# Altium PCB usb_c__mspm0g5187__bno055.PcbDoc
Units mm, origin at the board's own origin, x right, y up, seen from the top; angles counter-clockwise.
Board outline 92 x 60 mm, 2 copper layers (Top, Bottom), stack 0 mm thick; 42 components, 34 nets, 214 pads, 75 vias.
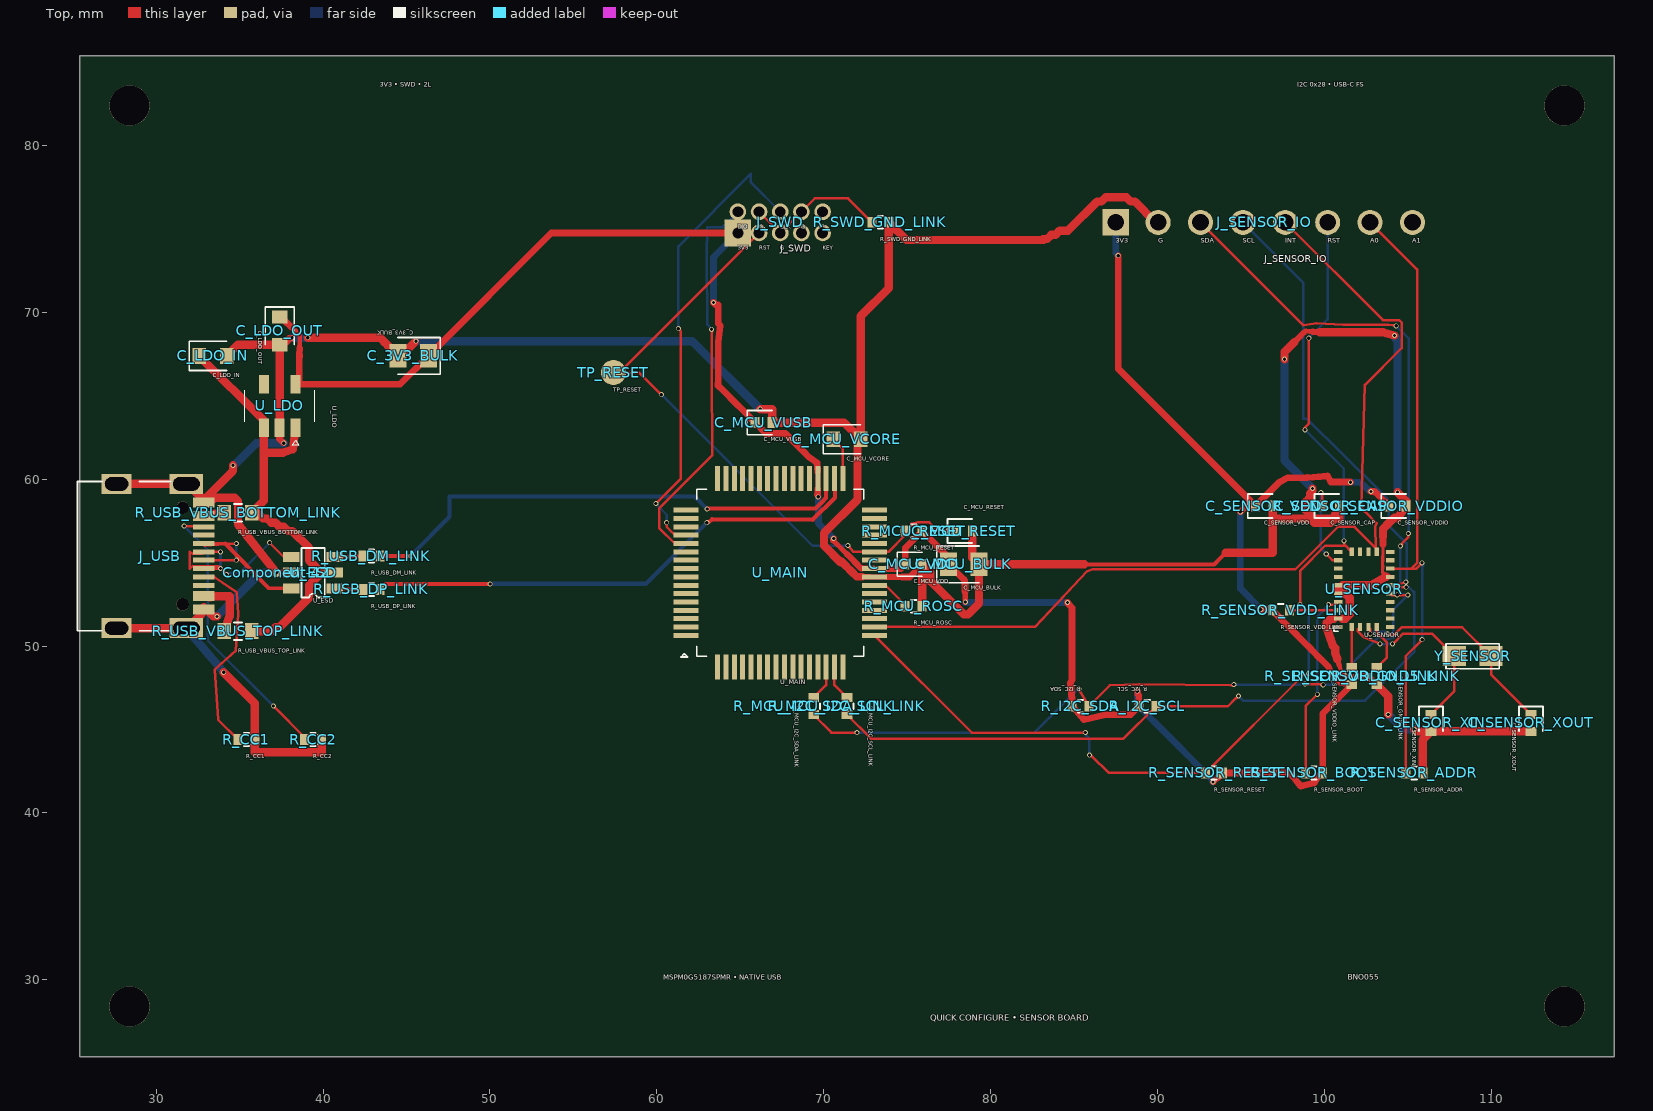
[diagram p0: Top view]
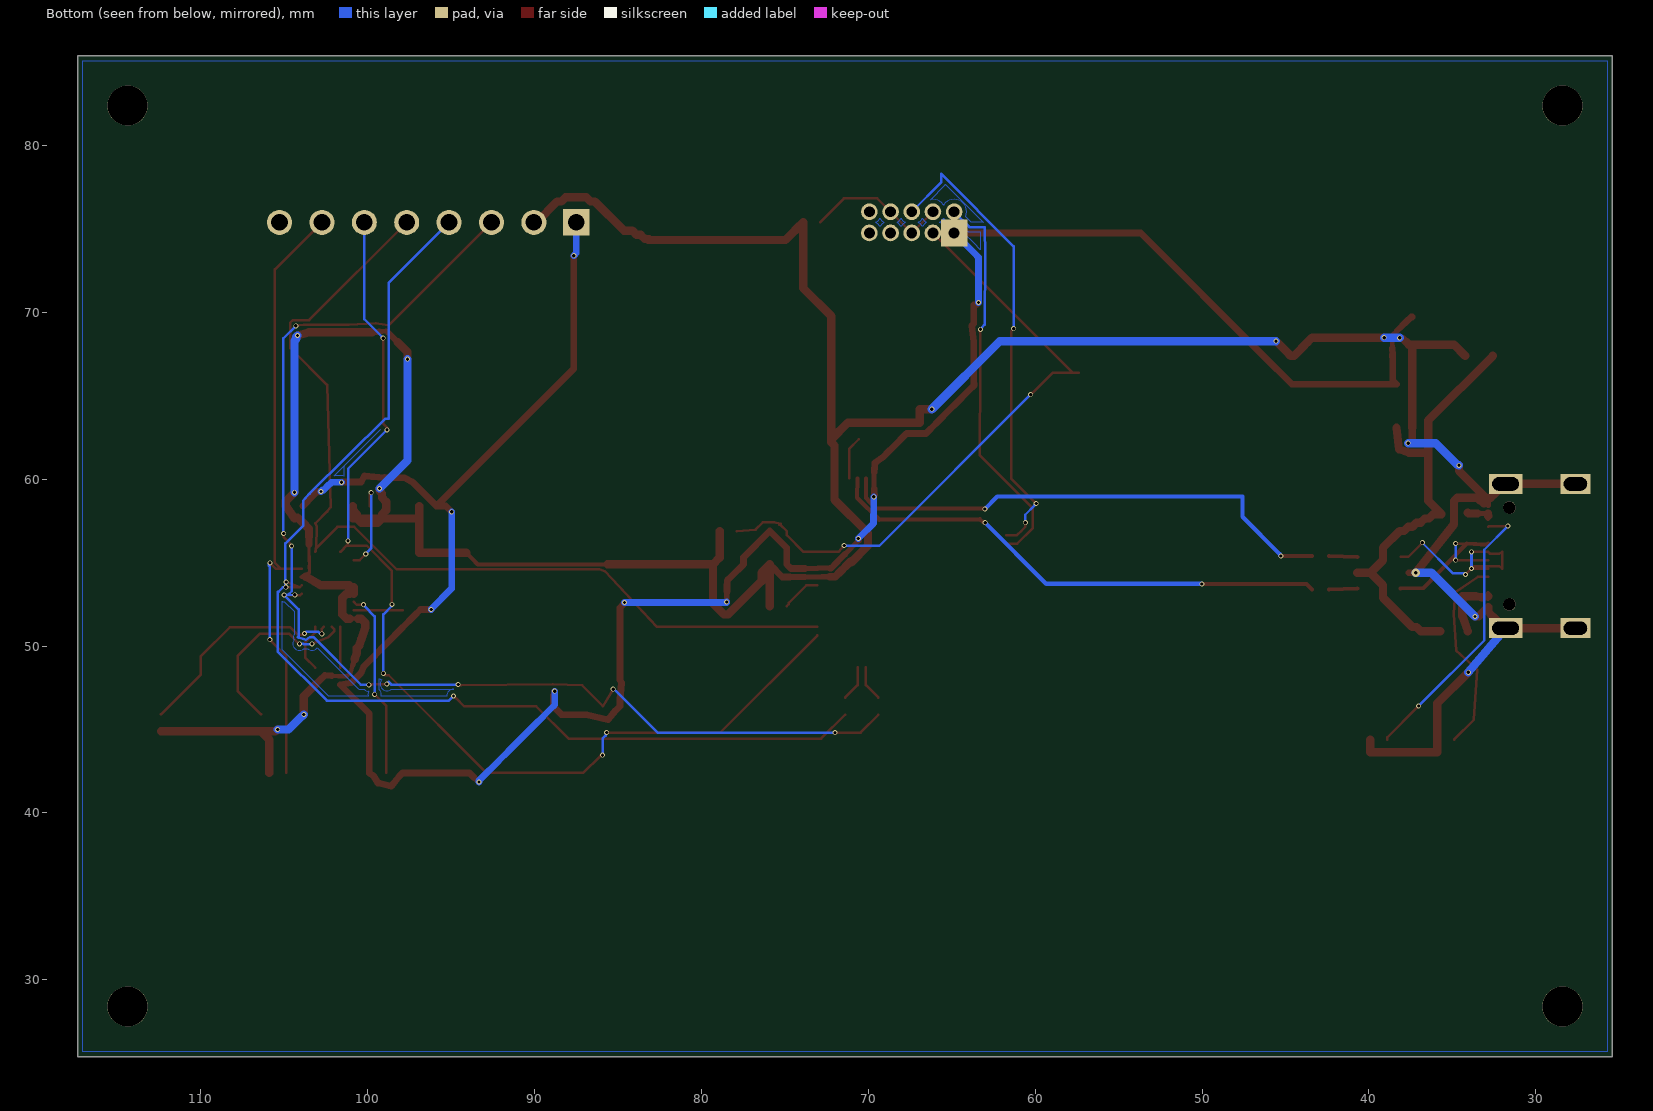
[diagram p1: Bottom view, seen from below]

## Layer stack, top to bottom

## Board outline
25.4,85.4 117.4,85.4 117.4,25.4 25.4,25.4

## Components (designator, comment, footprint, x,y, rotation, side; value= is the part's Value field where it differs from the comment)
C_3V3_BULK "" TSCIRCUIT-2.8500x1.4000mm 45.4,67.4 r180 top
C_LDO_IN "" TSCIRCUIT-2.4500x0.9500mm 33.4,67.4 r0 top
C_LDO_OUT "" TSCIRCUIT-0.9500x2.4500mm 37.4,68.9 r270 top
C_MCU_BULK "" TSCIRCUIT-2.8500x1.4000mm 78.4,54.9 r0 top
C_MCU_RESET "" TSCIRCUIT-1.5600x0.6400mm 78.4,56.9 r0 top
C_MCU_VCORE "" TSCIRCUIT-2.4500x0.9500mm 71.4,62.4 r0 top
C_MCU_VDD "" TSCIRCUIT-1.5600x0.6400mm 75.4,54.9 r0 top
C_MCU_VUSB "" TSCIRCUIT-1.5600x0.6400mm 66.4,63.4 r0 top
C_SENSOR_CAP "" TSCIRCUIT-1.5600x0.6400mm 100.4,58.4 r0 top
C_SENSOR_VDD "" TSCIRCUIT-1.5600x0.6400mm 96.4,58.4 r0 top
C_SENSOR_VDDIO "" TSCIRCUIT-1.5600x0.6400mm 104.4,58.4 r0 top
C_SENSOR_XIN "" TSCIRCUIT-0.6400x1.5600mm 106.4,45.4 r270 top
C_SENSOR_XOUT "" TSCIRCUIT-0.6400x1.5600mm 112.4,45.4 r270 top
Component-42 "" TSCIRCUIT-0.5000x0.5000mm 37.2,54.4 r0 top
J_SENSOR_IO "" TSCIRCUIT-19.2800x1.5000mm 96.4,75.4 r0 top
J_SWD "" TSCIRCUIT-6.0800x2.2700mm 67.4,75.4 r0 top
J_USB "" TSCIRCUIT-6.7732x9.8502mm 30.113,55.4 r90 top
R_CC1 "" TSCIRCUIT-1.5600x0.6400mm 35.4,44.4 r0 top
R_CC2 "" TSCIRCUIT-1.5600x0.6400mm 39.4,44.4 r0 top
R_I2C_SCL "" TSCIRCUIT-1.5600x0.6400mm 89.4,46.4 r180 top
R_I2C_SDA "" TSCIRCUIT-1.5600x0.6400mm 85.4,46.4 r180 top
R_MCU_I2C_SCL_LINK "" TSCIRCUIT-0.6400x1.5600mm 71.4,46.4 r270 top
R_MCU_I2C_SDA_LINK "" TSCIRCUIT-0.6400x1.5600mm 69.4,46.4 r270 top
R_MCU_RESET "" TSCIRCUIT-1.5600x0.6400mm 75.4,56.9 r0 top
R_MCU_ROSC "" TSCIRCUIT-1.5600x0.6400mm 75.4,52.4 r0 top
R_SENSOR_ADDR "" TSCIRCUIT-1.5600x0.6400mm 105.4,42.4 r0 top
R_SENSOR_BOOT "" TSCIRCUIT-1.5600x0.6400mm 99.4,42.4 r0 top
R_SENSOR_GND5_LINK "" TSCIRCUIT-0.6400x1.5600mm 103.15,48.2 r270 top
R_SENSOR_RESET "" TSCIRCUIT-1.5600x0.6400mm 93.4,42.4 r0 top
R_SENSOR_VDD_LINK "" TSCIRCUIT-1.5600x0.6400mm 97.4,52.15 r0 top
R_SENSOR_VDDIO_LINK "" TSCIRCUIT-0.6400x1.5600mm 101.65,48.2 r270 top
R_SWD_GND_LINK "" TSCIRCUIT-1.5600x0.6400mm 73.4,75.4 r0 top
R_USB_DM_LINK "" TSCIRCUIT-1.5600x0.6400mm 42.9,55.4 r0 top
R_USB_DP_LINK "" TSCIRCUIT-1.5600x0.6400mm 42.9,53.4 r0 top
R_USB_VBUS_BOTTOM_LINK "" TSCIRCUIT-2.4500x0.9500mm 34.9,58 r0 top
R_USB_VBUS_TOP_LINK "" TSCIRCUIT-2.4500x0.9500mm 34.9,50.9 r0 top
TP_RESET "" TSCIRCUIT-1.5000x1.5000mm 57.4,66.4 r0 top
U_ESD "" TSCIRCUIT-3.6000x2.5000mm 39.4,54.4 r0 top
U_LDO "" TSCIRCUIT-2.5000x3.7000mm 37.4,64.4 r270 top
U_MAIN "" TSCIRCUIT-12.8000x12.8000mm 67.4,54.4 r0 top
U_SENSOR "" TSCIRCUIT-3.6260x4.9999mm 102.4,53.4 r0 top
Y_SENSOR "" TSCIRCUIT-3.6000x1.2000mm 108.9,49.4 r0 top

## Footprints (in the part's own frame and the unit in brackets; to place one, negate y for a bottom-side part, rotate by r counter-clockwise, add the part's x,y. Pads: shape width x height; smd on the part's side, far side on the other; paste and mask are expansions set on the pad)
TSCIRCUIT-0.5000x0.5000mm [mm]
TSCIRCUIT-0.6400x1.5600mm [mm]
  rect 0.54x0.64 smd: 1(-0.51,0) 2(0.51,0)
  silkscreen extent -0.98,-0.72 0.51,0.72
TSCIRCUIT-0.9500x2.4500mm [mm]
  rect 0.8x0.95 smd: 1(-0.825,0) 2(0.825,0)
  silkscreen extent -1.43,-0.87 0.82,0.88
TSCIRCUIT-1.5000x1.5000mm [mm]
  round 1.5 smd: 1(0,0)
TSCIRCUIT-1.5600x0.6400mm [mm]
  rect 0.54x0.64 smd: 1(-0.51,0) 2(0.51,0)
  silkscreen extent -0.98,-0.72 0.51,0.72
TSCIRCUIT-2.4500x0.9500mm [mm]
  rect 0.8x0.95 smd: 1(-0.825,0) 2(0.825,0)
  silkscreen extent -1.42,-0.87 0.82,0.87
TSCIRCUIT-2.5000x3.7000mm [mm]
  rect 1.1x0.6 smd: 1(1.3,0.95) 2(1.3,0) 3(1.3,-0.95) 4(-1.3,-0.95) 5(-1.3,0.95)
  silkscreen extent -0.95,-2.1 2.35,2.1
TSCIRCUIT-2.8500x1.4000mm [mm]
  rect 1.025x1.4 smd: 1(-0.913,0) 2(0.913,0)
  silkscreen extent -1.63,-1.1 0.91,1.1
TSCIRCUIT-3.6000x1.2000mm [mm]
  rect 1.4x1.2 smd: 1(-1.1,0) 2(1.1,0)
  silkscreen extent -1.6,-0.75 1.6,0.75
TSCIRCUIT-3.6000x2.5000mm [mm]
  rect 1x0.6 smd: 1(-1.3,-0.95) 2(-1.3,0) 3(-1.3,0.95) 4(1.3,0.95) 5(1.3,0) 6(1.3,-0.95)
  silkscreen extent -0.7,-1.49 0.7,1.49
TSCIRCUIT-3.6260x4.9999mm [mm]
  rect 0.5x0.25 smd: 1(-1.563,-2.25) 2(-1.563,-1.75) 3(-1.563,-1.25) 4(-1.563,-0.75) 5(-1.563,-0.25) 6(-1.563,0.25) 7(-1.563,0.75) 8(-1.563,1.25) 9(-1.563,1.75) 10(-1.563,2.25) 15(1.563,2.25) 16(1.563,1.75) 17(1.563,1.25) 18(1.563,0.75) 19(1.563,0.25) 20(1.563,-0.25) 21(1.563,-0.75) 22(1.563,-1.25) 23(1.563,-1.75) 24(1.563,-2.25)
  rect 0.25x0.5 smd: 11(-0.75,2.25) 12(-0.25,2.25) 13(0.25,2.25) 14(0.75,2.25) 25(0.75,-2.25) 26(0.25,-2.25) 27(-0.25,-2.25) 28(-0.75,-2.25)
  silkscreen extent -1.81,-2.5 -1.56,-2.25
TSCIRCUIT-6.0800x2.2700mm [mm]
  rect 1.6x1.6 hole 0.65: 1(-2.54,-0.635)
  round 1 hole 0.65: 2(-2.54,0.635) 3(-1.27,0.635) 4(0,0.635) 5(1.27,0.635) 6(2.54,0.635) 7(2.54,-0.635) 8(1.27,-0.635) 9(0,-0.635) 10(-1.27,-0.635)
TSCIRCUIT-6.7732x9.8502mm [mm]
  rect 0.3x1.3 smd: 1(-3.35,-2.737) 2(-3.05,-2.737) 3(-2.55,-2.737) 4(-2.25,-2.737) 5(-1.75,-2.737) 6(-1.25,-2.737) 7(-0.75,-2.737) 8(-0.25,-2.737) 9(0.25,-2.737) 10(0.75,-2.737) 11(1.25,-2.737) 12(1.75,-2.737) 13(2.55,-2.737) 14(2.25,-2.737) 15(3.35,-2.737) 16(3.05,-2.737)
  rect 1.2x2 hole 0.8 slot 1.6 at 90 deg: 17(-4.325,-1.693) 18(4.325,-1.693)
  rect 1.2x1.8 hole 0.8 slot 1.4 at 90 deg: 19(4.325,2.487) 20(-4.325,2.487)
  round 0.75 hole 0.75 unplated: NPTH-1(-2.9,-1.468) NPTH-2(2.9,-1.468)
  silkscreen extent -4.47,-0.75 4.47,4.83
TSCIRCUIT-12.8000x12.8000mm [mm]
  rect 1.5x0.3 smd: 1(-5.65,-3.75) 2(-5.65,-3.25) 3(-5.65,-2.75) 4(-5.65,-2.25) 5(-5.65,-1.75) 6(-5.65,-1.25) 7(-5.65,-0.75) 8(-5.65,-0.25) 9(-5.65,0.25) 10(-5.65,0.75) 11(-5.65,1.25) 12(-5.65,1.75) 13(-5.65,2.25) 14(-5.65,2.75) 15(-5.65,3.25) 16(-5.65,3.75) 33(5.65,3.75) 34(5.65,3.25) 35(5.65,2.75) 36(5.65,2.25) 37(5.65,1.75) 38(5.65,1.25) 39(5.65,0.75) 40(5.65,0.25) 41(5.65,-0.25) 42(5.65,-0.75) 43(5.65,-1.25) 44(5.65,-1.75) 45(5.65,-2.25) 46(5.65,-2.75) 47(5.65,-3.25) 48(5.65,-3.75)
  rect 0.3x1.5 smd: 17(-3.75,5.65) 18(-3.25,5.65) 19(-2.75,5.65) 20(-2.25,5.65) 21(-1.75,5.65) 22(-1.25,5.65) 23(-0.75,5.65) 24(-0.25,5.65) 25(0.25,5.65) 26(0.75,5.65) 27(1.25,5.65) 28(1.75,5.65) 29(2.25,5.65) 30(2.75,5.65) 31(3.25,5.65) 32(3.75,5.65) 49(3.75,-5.65) 50(3.25,-5.65) 51(2.75,-5.65) 52(2.25,-5.65) 53(1.75,-5.65) 54(1.25,-5.65) 55(0.75,-5.65) 56(0.25,-5.65) 57(-0.25,-5.65) 58(-0.75,-5.65) 59(-1.25,-5.65) 60(-1.75,-5.65) 61(-2.25,-5.65) 62(-2.75,-5.65) 63(-3.25,-5.65) 64(-3.75,-5.65)
  silkscreen extent -5.95,-5.05 5,5
TSCIRCUIT-19.2800x1.5000mm [mm]
  rect 1.6x1.6 hole 1: 1(-8.89,0)
  round 1.5 hole 1: 2(-6.35,0) 3(-3.81,0) 4(-1.27,0) 5(1.27,0) 6(3.81,0) 7(6.35,0) 8(8.89,0)

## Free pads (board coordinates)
  round 2.4 hole 2.4 unplated: NPTH-3(28.4,28.4) NPTH-4(114.4,28.4) NPTH-5(28.4,82.4) NPTH-6(114.4,82.4)

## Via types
v1: diameter 0.3, hole 0.2, Top to Bottom, 74 vias
v2: diameter 0.5, hole 0.2, Top to Bottom, 1 vias

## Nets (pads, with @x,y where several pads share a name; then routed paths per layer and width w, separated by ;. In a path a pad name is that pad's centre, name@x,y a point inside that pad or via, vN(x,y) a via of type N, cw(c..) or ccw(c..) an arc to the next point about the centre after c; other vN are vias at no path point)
".J_SWD > .pin2 to .U_MAIN > .pin12": J_SWD.2 U_MAIN.12 | length 23.7
  Top w0.15: U_MAIN.12 61.077,56.15 60.139,57.089 60.139,58.257 63.316,61.435 63.28,66.534 63.285,68.668 63.316,68.934 63.316,68.986 v1(63.28,68.991)
  Bottom w0.15: v1(63.28,68.991) 63.028,69.274 63.003,73.368 63.028,75.122 63.947,75.122 J_SWD.2
".J_SWD > .pin4 to .U_MAIN > .pin13": J_SWD.4 U_MAIN.13 | length 28.3
  Top w0.15: v1(59.946,58.55) 61.441,60.045 61.441,68.856 61.441,68.875 v1(61.291,69.025) ; v1(60.595,57.398) 60.595,57.154 60.843,56.887 61.098,56.649 U_MAIN.13
  Bottom w0.15: v1(59.946,58.55) 60.051,58.445 60.051,58.421 60.595,57.877 v1(60.595,57.398) ; v1(61.291,69.025) 61.291,73.965 65.628,78.302 65.628,77.807 J_SWD.4
".U_MAIN > .pin42 to .R_MCU_ROSC > .pin1": R_MCU_ROSC.1 U_MAIN.42 | length 2.4
  Top w0.15: U_MAIN.42 73.719,53.65 74.769,52.6 74.769,52.521 R_MCU_ROSC.1
".U_SENSOR > .CAP to .C_SENSOR_CAP > .pin1": C_SENSOR_CAP.1 U_SENSOR.9 | length 5.5
  Top w0.15: v1(99.799,59.199) 99.829,59.171 99.829,59.125 99.89,59.063 C_SENSOR_CAP.1 ; v1(100.125,55.523) 100.498,55.15 U_SENSOR.9
  Bottom w0.15: v1(99.799,59.199) 99.8,55.861 100.089,55.572 100.089,55.559 v1(100.125,55.523)
BNO055_GND5_LOCAL: R_SENSOR_GND5_LINK.1 U_SENSOR.25 | length 2.9
  Top w0.15: R_SENSOR_GND5_LINK.1 103.76,49.32 103.756,50.209 103.151,50.818 U_SENSOR.25
BNO055_VDD_LOCAL: R_SENSOR_VDD_LINK.2 U_SENSOR.3 | length 2.9
  Top w0.15: R_SENSOR_VDD_LINK.2 U_SENSOR.3@100.837,52.15
BNO055_VDDIO_LOCAL: R_SENSOR_VDDIO_LINK.1 U_SENSOR.28 | length 2.4
  Top w0.15: R_SENSOR_VDDIO_LINK.1 U_SENSOR.28
GND: C_3V3_BULK.2 C_LDO_IN.2 C_LDO_OUT.2 C_MCU_BULK.2 C_MCU_RESET.2 C_MCU_VCORE.2 C_MCU_VDD.2 C_MCU_VUSB.2 C_SENSOR_CAP.2 C_SENSOR_VDD.2 C_SENSOR_VDDIO.2 C_SENSOR_XIN.2 C_SENSOR_XOUT.2 J_SENSOR_IO.2 J_USB.1 J_USB.2 J_USB.15 J_USB.16 J_USB.17 J_USB.18 J_USB.19 J_USB.20 R_CC1.2 R_CC2.2 R_MCU_ROSC.2 R_SENSOR_ADDR.2 R_SENSOR_GND5_LINK.2 R_SWD_GND_LINK.2 U_ESD.2 U_LDO.2 U_MAIN.41 U_SENSOR.2 U_SENSOR.5 U_SENSOR.6 U_SENSOR.18 | length 241.4
  Top w0.188: 103.506,54.823 103.512,55.247 103.518,55.67 103.523,56.093
  Top w0.2: 103.506,54.823 103.5,54.4 103.889,54.224 U_SENSOR.18
  Top w0.25: 85.632,54.9 86.118,54.9 86.604,54.9 87.09,54.9 87.577,54.9 88.063,54.9 88.549,54.9 89.035,54.9 89.521,54.9 90.007,54.9 90.493,54.9 90.979,54.9 91.466,54.9 91.952,54.9 92.438,54.9 92.924,54.9 93.41,54.9 93.76,55.25 94.11,55.6 ; U_SENSOR.2@100.587,51.65 U_SENSOR.2 101.087,51.65 ; U_SENSOR.5 101.087,53.15 ; 100.837,53.525 U_SENSOR.6 100.931,53.65 101.024,53.65 101.087,53.65 101.118,53.65 ; 100.918,48.806 101.05,48.4 101.25,48.2 101.75,48.2 102.165,48.225 ; U_SENSOR.18@103.713,54.15 U_SENSOR.18
  Top w0.275: J_USB.16 J_USB.16@33.1,58.5
  Top w0.3: J_USB.1@32.699,51.9 J_USB.1 J_USB.1@32.849,52.2 ; J_USB.15@32.699,58.9 J_USB.15 ; J_USB.2 J_USB.1@32.999,52.2 ; J_USB.16@32.849,58.6 J_USB.15 ; J_USB.15@32.999,58.9 J_USB.15 ; U_MAIN.41@72.769,54.15 72.863,54.15 72.956,54.15 U_MAIN.41 73.144,54.15 73.237,54.15 73.331,54.15 73.425,54.15 73.519,54.15 73.612,54.15 73.706,54.15 U_MAIN.41@73.8,54.15
  Top w0.312: 98.795,68.806 98.9,68.89 99.323,68.848 ; 100.786,49.211 100.918,48.806
  Top w0.32: 72.3,54.156 72.376,54.155 U_MAIN.41@72.769,54.15
  Top w0.325: J_USB.16 J_USB.16@32.849,58.6
  Top w0.35: v1@37.624,62.19 v1(37.643,62.171) ; 37.968,68.441 38.124,68.441 v1(38.153,68.477) ; 98.503,68.514 98.795,68.806
  Top w0.375: 37.4,62.417 37.624,62.193 v1@37.624,62.19 ; 45.429,68.145 45.435,68.145 v1(45.568,68.278) ; U_MAIN.41@73.8,54.15 74.253,54.15 74.707,54.15 ; 98.211,68.222 98.503,68.514 ; 102.165,48.225 102.58,48.25
  Top w0.4: J_USB.16@33.1,58.5 J_USB.15@33.3,58.7 ; 37.2,54.4 U_ESD.2@37.6,54.4 ; 74.707,54.15 75.16,54.15 75.41,54.4 75.66,54.65 C_MCU_VDD.2 ; 99.323,68.848 99.746,68.806 ; 102.58,48.25 102.865,47.97 R_SENSOR_GND5_LINK.2
  Top w0.425: C_LDO_OUT.2@37.785,68.258 37.968,68.441 ; 103.523,56.093 103.524,56.561
  Top w0.45: 37.4,62.417 37.4,62.758 U_LDO.2 ; 71.983,54.16 72.3,54.156
  Top w0.475: 71.351,54.792 71.667,54.476 71.983,54.16
  Top w0.5: J_USB.20 J_USB.17 31.874,51.075 32.474,51.675 32.699,51.9 ; J_USB.19 J_USB.18 31.874,59.725 32.474,59.125 32.699,58.9 ; J_USB.1@32.849,52.2 J_USB.2 ; J_USB.1@32.999,52.2 33.42,51.779 v1(33.639,51.779) ; 32.999,58.9 34.603,60.504 v1(34.603,60.841) ; J_USB.15@33.3,58.7 33.5,58.9 34.7,58.9 34.9,58.7 34.9,57.3 37.2,54.4 ; v1(34.043,48.435) 35.91,46.568 R_CC1.2 35.91,43.65 39.91,43.65 R_CC2.2 ; C_LDO_IN.2 34.9,68.075 C_LDO_OUT.2 ; U_LDO.2 C_LDO_OUT.2 ; C_LDO_OUT.2@37.785,68.258 37.603,68.075 C_LDO_OUT.2 ; v1(39.081,68.491) 39.56,68.491 40.04,68.491 40.519,68.491 40.999,68.491 41.478,68.491 41.958,68.491 42.437,68.491 42.917,68.491 43.396,68.491 43.669,68.218 43.942,67.946 44.215,67.673 C_3V3_BULK.2 44.683,67.4 44.932,67.648 45.18,67.897 45.429,68.145 ; v1(66.2,64.2) 66.91,64.2 C_MCU_VUSB.2 71.225,63.4 C_MCU_VCORE.2 ; 71.351,54.792 71.035,55.108 71.025,55.098 71.025,55.025 70.025,56.025 70.025,56.775 72.025,58.775 72.025,62.025 72.225,62.225 C_MCU_VCORE.2 ; R_MCU_ROSC.2 C_MCU_VDD.2 75.91,54.89 76.4,54.4 76.4,53.9 78.4,51.9 78.65,51.9 79.313,52.563 C_MCU_BULK.2 ; C_MCU_RESET.2 78.91,55.303 C_MCU_BULK.2 ; 85.632,54.9 85.146,54.9 84.66,54.9 84.174,54.9 83.688,54.9 83.201,54.9 82.715,54.9 82.229,54.9 81.743,54.9 81.257,54.9 80.771,54.9 80.285,54.9 79.799,54.9 C_MCU_BULK.2 ; J_SENSOR_IO.2 89.9,75.4 88.65,76.65 88.4,76.65 88.15,76.9 86.9,76.9 86.65,76.65 86.4,76.65 84.65,74.9 84.15,74.9 83.9,74.65 83.65,74.65 83.4,74.4 83.15,74.4 83.15,74.394 83.199,74.345 82.716,74.345 82.233,74.345 81.75,74.345 81.267,74.345 80.784,74.345 80.301,74.345 79.818,74.345 79.335,74.345 78.851,74.345 78.368,74.345 77.885,74.345 77.402,74.345 76.919,74.345 76.436,74.345 75.953,74.345 75.47,74.345 74.987,74.345 74.965,74.345 74.613,74.697 74.262,75.048 R_SWD_GND_LINK.2 73.91,71.464 72.225,69.779 72.225,69.287 72.225,68.795 72.225,68.303 72.225,67.812 72.225,67.32 72.225,66.828 72.225,66.336 72.225,65.844 72.225,65.352 72.225,64.86 72.225,64.368 72.225,63.876 72.225,63.384 72.225,62.892 C_MCU_VCORE.2 ; 94.11,55.6 96.91,55.6 C_SENSOR_VDD.2 96.91,57.65 100.91,57.65 C_SENSOR_CAP.2 100.9,58.4 100.9,58.15 100.65,57.9 100.65,57.65 100.4,57.4 99.4,57.4 99.15,57.65 99.15,57.9 98.9,58.15 98.9,58.65 99.15,58.9 99.15,59.15 99.305,59.305 v1(99.305,59.445) ; v1(97.623,67.197) 97.627,67.201 97.627,67.294 97.627,67.638 97.919,67.93 98.211,68.222 ; 99.746,68.806 100.221,68.806 100.696,68.806 101.172,68.806 101.647,68.806 102.122,68.806 102.598,68.806 103.073,68.806 103.549,68.806 v1(104.214,68.616) ; U_SENSOR.2@100.587,51.65 100.4,51.65 100.15,51.4 100.15,51.15 100.391,50.428 100.523,50.022 100.654,49.89 100.654,49.617 100.786,49.211 ; U_SENSOR.5 100.837,53.275 100.837,53.525 ; 101.087,51.65 101.275,51.65 101.525,51.9 101.525,52.9 101.275,53.15 101.087,53.15 ; 101.118,53.65 101.212,53.65 101.306,53.65 101.4,53.65 101.493,53.65 101.587,53.65 101.994,53.65 102.401,53.65 102.807,53.65 103.65,54.15 103.713,54.15 ; R_SENSOR_GND5_LINK.2 103.837,47.003 v1(103.837,45.907) ; 103.524,56.561 103.525,57.028 103.871,57.371 104.217,57.714 104.4,57.65 C_SENSOR_VDDIO.2 104.91,58.698 v1(104.393,59.215) ; v1(105.4,45) 105.411,44.989 105.441,44.989 105.54,44.89 C_SENSOR_XIN.2 ; R_SENSOR_ADDR.2 105.91,44.4 C_SENSOR_XIN.2 ; C_SENSOR_XOUT.2 C_SENSOR_XIN.2
  Bottom w0.5: J_USB.17 v1(34.043,48.435) ; v1(33.639,51.779) 36.26,54.4 37.2,54.4 ; v1(34.603,60.841) 34.622,60.86 34.687,60.86 35.015,61.188 35.343,61.516 35.67,61.843 35.998,62.171 36.409,62.171 36.82,62.171 37.232,62.171 v1(37.643,62.171) ; v1(38.153,68.477) 39.067,68.477 v1(39.081,68.491) ; v1(45.568,68.278) 46.065,68.278 46.562,68.278 47.059,68.278 47.556,68.278 48.053,68.278 48.55,68.278 49.047,68.278 49.544,68.278 50.041,68.278 50.538,68.278 51.036,68.278 51.533,68.278 52.03,68.278 52.527,68.278 53.024,68.278 53.521,68.278 54.018,68.278 54.515,68.278 55.012,68.278 55.509,68.278 56.006,68.278 56.503,68.278 57,68.278 57.497,68.278 57.994,68.278 58.491,68.278 62.122,68.278 v1(66.2,64.2) ; v1(97.623,67.197) 97.623,66.73 97.623,66.263 97.623,65.796 97.623,65.329 97.623,64.862 97.623,64.395 97.623,63.929 97.623,63.462 97.623,62.995 97.623,62.528 97.623,62.061 97.623,61.594 97.623,61.127 97.934,60.816 98.246,60.504 98.557,60.193 98.868,59.882 99.179,59.571 v1(99.305,59.445) ; v1(103.837,45.907) 103.96,45.784 103.976,45.784 104.759,45 v1(105.4,45) ; v1(104.214,68.616) 104.283,68.547 104.283,68.418 104.393,68.308 104.393,67.83 104.393,67.351 104.393,66.873 104.393,66.394 104.393,65.915 104.393,65.437 104.393,64.958 104.393,64.48 104.393,64.001 104.393,63.522 104.393,63.044 104.393,62.565 104.393,62.087 104.393,61.608 104.393,61.129 104.393,60.651 104.393,60.172 104.393,59.694 v1(104.393,59.215)
MAIN_RESET: C_MCU_RESET.1 J_SWD.10 R_MCU_RESET.1 TP_RESET.1 U_MAIN.38 | length 38.4
  Top w0.15: v1(60.276,65.077) 60.178,65.175 60.157,65.175 58.932,66.4 TP_RESET.1 57.765,66.4 J_SWD.10 ; v1(71.452,56.032) 71.798,55.65 U_MAIN.38 73.889,55.65 74.889,56.651 R_MCU_RESET.1@74.889,56.899 ; R_MCU_RESET.1 75.256,57.266 75.34,57.266 75.256,57.35 75.65,57.423 75.9,57.425 76.15,57.425 76.323,57.425 76.764,56.984 C_MCU_RESET.1
  Bottom w0.15: v1(60.276,65.077) 69.336,56.017 71.271,56.017 71.431,56.017 v1(71.452,56.032)
MCU_I2C_SCL_LOCAL: R_MCU_I2C_SCL_LINK.1 U_MAIN.50 | length 2.2
  Top w0.15: U_MAIN.50 70.65,47.66 R_MCU_I2C_SCL_LINK.1
MCU_I2C_SDA_LOCAL: R_MCU_I2C_SDA_LINK.1 U_MAIN.51 | length 2.2
  Top w0.15: R_MCU_I2C_SDA_LINK.1 70.15,47.66 U_MAIN.51
MSPM0_VCORE: C_MCU_VCORE.1 U_MAIN.32 | length 2.6
  Top w0.15: C_MCU_VCORE.1 71.15,61.825 U_MAIN.32
SENSOR_ADDR0: J_SENSOR_IO.7 R_SENSOR_ADDR.1 U_SENSOR.17 | length 38.4
  Top w0.15: J_SENSOR_IO.7 105.57,72.58 105.57,54.99 105.23,54.65 U_SENSOR.17 105.522,54.65 v1(105.862,54.99) ; R_SENSOR_ADDR.1 104.89,49.403 105.772,50.285 105.772,50.29 v1(105.875,50.393)
  Bottom w0.15: v1(105.862,54.99) 105.94,54.912 105.94,54.819 105.875,54.754 v1(105.875,50.393)
SENSOR_ADDR1: J_SENSOR_IO.8
SENSOR_BOOT: R_SENSOR_BOOT.1 U_SENSOR.4 | length 11.3
  Top w0.15: R_SENSOR_BOOT.1 98.89,46.413 99.588,47.111 v1(99.592,47.115) ; v1(100.262,52.49) 100.67,52.483 U_SENSOR.4
  Bottom w0.15: v1(99.592,47.115) 99.592,51.782 100.212,52.402 100.212,52.433 v1(100.262,52.49)
SENSOR_INT: J_SENSOR_IO.5 U_MAIN.47 U_SENSOR.14 | length 57.9
  Top w0.15: U_MAIN.47 82.673,51.151 85.8,54.5 86.121,54.599 98.266,54.6 100.815,57.147 101.829,57.146 103.114,55.861 103.114,55.686 U_SENSOR.14 103.081,55.936 103.047,57.154 103.15,57.36 102.447,58.063 102.225,58.325 102.447,65.657 104.651,67.861 104.652,69.39 104.495,69.546 103.524,69.546 J_SENSOR_IO.5
SENSOR_RESET: J_SENSOR_IO.6 R_SENSOR_RESET.1 U_MAIN.48 U_SENSOR.11 | length 64.3
  Top w0.15: U_MAIN.48 78.88,44.82 v1(85.69,44.82) ; v1(85.934,43.471) 85.976,43.429 86.066,43.429 87.095,42.4 R_SENSOR_RESET.1 98.749,48.259 98.963,48.259 v1(99.07,48.366) ; v1(98.554,52.509) 98.555,54.513 100.067,56.025 101.273,56.027 U_SENSOR.11 101.19,56.11 v1(101.19,56.311) ; v1(98.847,62.969) 98.818,62.998 98.818,63.073 99.081,63.336 v1(99.081,68.463)
  Bottom w0.15: v1(85.69,44.82) 85.748,44.762 85.748,44.643 85.934,44.456 v1(85.934,43.471) ; v1(98.554,52.509) 98.568,52.495 98.568,52.407 99.07,51.904 v1(99.07,48.366) ; v1(98.847,62.969) 101.182,60.634 101.182,56.438 101.182,56.319 v1(101.19,56.311) ; v1(99.081,68.463) 99.191,68.573 100.21,69.592 J_SENSOR_IO.6
SENSOR_SCL: J_SENSOR_IO.4 R_I2C_SCL.1 R_MCU_I2C_SCL_LINK.2 U_SENSOR.19 | length 69.6
  Top w0.15: R_MCU_I2C_SCL_LINK.2 72.837,44.458 87.966,44.456 R_I2C_SCL.1 94.228,46.4 94.71,46.882 94.737,46.882 v1(94.865,47.01) ; v1(104.9,53.85) U_SENSOR.19@104.073,53.54 ; v1(104.911,53.54) U_SENSOR.19@104.073,53.54 ; U_SENSOR.19@104.073,53.54 U_SENSOR.19 U_SENSOR.19@104.073,53.54
  Bottom w0.15: v1(94.865,47.01) 95.141,46.734 102.458,46.734 105.408,49.684 105.408,53.26 105.354,53.26 105.085,53.53 104.921,53.53 v1(104.9,53.85) ; J_SENSOR_IO.4 98.736,71.794 98.736,63.644 98.947,63.644 103.49,59.149 103.877,58.713 103.877,57.212 104.935,56.153 104.935,53.654 104.935,53.564 v1(104.911,53.54)
SENSOR_SDA: J_SENSOR_IO.3 R_I2C_SDA.1 R_MCU_I2C_SDA_LINK.2 U_SENSOR.20 | length 75.2
  Top w0.15: R_MCU_I2C_SDA_LINK.2 70.47,44.82 71.957,44.82 v1(71.996,44.816) ; v1(85.291,47.423) R_I2C_SDA.1 87.151,47.647 88.93,47.702 94.396,47.643 94.525,47.641 v1(94.583,47.699) ; J_SENSOR_IO.3 98.765,69.225 99.525,69.35 101.158,69.256 103.849,69.253 104.148,69.225 104.287,69.225 v1(104.312,69.198) ; v1(98.861,47.73) 99.75,47.73 99.827,47.653 99.909,47.653 v1(99.941,47.685) ; v1(104.375,53.075) U_SENSOR.20@104.049,53.064 ; v1(104.562,56.004) 104.667,56.109 104.667,56.167 105.047,56.547 v1(105.047,56.756) ; v1(105.014,53.064) U_SENSOR.20@104.049,53.064 ; U_SENSOR.20@104.049,53.064 U_SENSOR.20 U_SENSOR.20@104.049,53.064
  Bottom w0.15: v1(71.996,44.816) 82.635,44.82 85.107,47.291 85.117,47.291 v1(85.291,47.423) ; v1(94.583,47.699) 98.584,47.699 98.738,47.853 v1(98.861,47.73) ; v1(99.941,47.685) 100.411,47.685 103.254,50.537 103.49,50.54 103.722,50.376 ; 103.723,50.376 104.187,50.534 104.147,50.519 104.147,52.198 104.986,53.036 v1(104.375,53.075) ; v1(104.312,69.198) 105.056,68.456 105.056,56.765 v1(105.047,56.756) ; v1(104.562,56.004) 104.562,53.289 104.761,53.09 104.937,53.09 104.987,53.04 104.989,53.04 v1(105.014,53.064)
SENSOR_XIN: C_SENSOR_XIN.1 U_SENSOR.27 Y_SENSOR.1 | length 11.3
  Top w0.15: U_SENSOR.27 102.003,51.003 102.003,50.901 102.378,50.526 v1(103.342,50.144) ; v1(104.096,50.144) 104.111,50.128 104.116,50.128 104.736,50.749 104.859,50.749 106.451,50.749 Y_SENSOR.1 107.8,47.31 C_SENSOR_XIN.1
  Bottom w0.15: v1(103.342,50.144) 103.37,50.121 103.574,50.11 103.85,50.111 103.88,50.149 v1(104.096,50.144)
SENSOR_XOUT: C_SENSOR_XOUT.1 U_SENSOR.26 Y_SENSOR.2 | length 13.2
  Top w0.15: U_SENSOR.26 102.762,51.038 v1(102.762,50.737) ; v1(103.798,50.76) 103.858,50.694 103.96,50.694 104.209,50.694 104.641,51.125 104.78,51.125 108.275,51.125 Y_SENSOR.2 110,48.31 C_SENSOR_XOUT.1
  Bottom w0.15: v1(102.762,50.737) 102.807,50.782 102.893,50.782 102.983,50.871 103.105,50.871 103.681,50.871 v1(103.798,50.76)
swd-ground-1-to-2: J_SWD.3 J_SWD.5 J_SWD.9 R_SWD_GND_LINK.1 | length 8.8
  Top w0.15: J_SWD.3 J_SWD.9 J_SWD.5 69.481,76.846 71.471,76.846 71.471,76.819 R_SWD_GND_LINK.1
usb-dm-device: R_USB_DM_LINK.1 U_ESD.4 | length 1.7
  Top w0.25: U_ESD.4 R_USB_DM_LINK.1
usb-dm-mcu: R_USB_DM_LINK.2 U_MAIN.30 | length 30.7
  Top w0.25: R_USB_DM_LINK.2 v1(45.28,55.4) ; v1(63.019,58.22) 63.039,58.24 63.095,58.24 69.511,58.256 69.921,58.651 70.132,58.882 U_MAIN.30
  Bottom w0.25: v1(45.28,55.4) 45.326,55.446 45.326,55.504 47.58,57.758 47.58,58.967 62.272,58.967 v1(63.019,58.22)
usb-dm-port-tie: J_USB.7 J_USB.9 U_ESD.3 | length 12.4
  Top w0.15: J_USB.7 v1(33.85,54.65) ; v1(33.85,55.65) J_USB.9 32.746,55.547 32.199,55.547 32.013,55.65 32.013,54.65 32.199,54.798 33.711,54.798 v1(34.212,54.297) ; v1(36.8,56.2) 36.8,56.192 37.642,55.35 U_ESD.3
  Bottom w0.15: v1(33.85,54.65) v1(33.85,55.65) ; v1(34.212,54.297) 34.273,54.358 34.314,54.358 34.958,54.358 v1(36.8,56.2)
usb-dp-device: R_USB_DP_LINK.1 U_ESD.6 | length 1.7
  Top w0.25: U_ESD.6 R_USB_DP_LINK.1
usb-dp-mcu: R_USB_DP_LINK.2 U_MAIN.31 | length 30.7
  Top w0.25: R_USB_DP_LINK.2 43.738,53.728 v1(50.013,53.728) ; v1(63.002,57.4) 63.041,57.439 63.137,57.439 63.3,57.602 69.345,57.575 70.689,58.893 U_MAIN.31
  Bottom w0.25: v1(50.013,53.728) 50.024,53.739 59.341,53.739 v1(63.002,57.4)
usb-dp-port-tie: J_USB.8 J_USB.10 U_ESD.1 | length 11.3
  Top w0.15: J_USB.8 v1(34.8,55.15) ; J_USB.10 v1(34.8,56.15)
  Top w0.25: J_USB.10 32.924,56.075 34.135,56.143 36.724,53.481 U_ESD.1
  Bottom w0.15: v1(34.8,55.15) v1(34.8,56.15)
USB_CC1: J_USB.6 R_CC1.1 | length 12.2
  Top w0.15: J_USB.6 33.468,54.15 34.814,53.235 34.904,51.947 34.776,49.732 33.503,48.6 33.7,45.589 R_CC1.1
USB_CC2: J_USB.12 R_CC2.1 | length 17
  Top w0.15: v1(31.668,57.197) 32.802,57.197 J_USB.12 ; v1(37.019,46.41) 37.075,46.354 38.89,44.539 R_CC2.1
  Bottom w0.15: v1(31.668,57.197) 31.672,57.193 33.086,55.779 33.086,50.343 v1(37.019,46.41)
USB_VBUS_BOTTOM_LOCAL: J_USB.13 J_USB.14 R_USB_VBUS_BOTTOM_LINK.1 | length 1.5
  Top w0.3: J_USB.14 J_USB.14@32.849,57.8 ; J_USB.13 32.927,57.95 33.005,57.95 33.083,57.95 33.161,57.95 33.239,57.95 33.317,57.95 33.394,57.95 33.472,57.95 33.499,57.95
  Top w0.475: J_USB.13@32.849,57.8 J_USB.13 ; 33.499,57.95 R_USB_VBUS_BOTTOM_LINK.1@33.762,57.95
  Top w0.5: R_USB_VBUS_BOTTOM_LINK.1@33.762,57.95 34.025,57.95 R_USB_VBUS_BOTTOM_LINK.1
USB_VBUS_TOP_LOCAL: J_USB.3 J_USB.4 R_USB_VBUS_TOP_LINK.1 | length 4
  Top w0.3: J_USB.4 32.849,53 J_USB.3 J_USB.3@33.225,52.925
  Top w0.5: J_USB.3@33.225,52.925 33.6,53 34.4,53 34.4,51.8 R_USB_VBUS_TOP_LINK.1
VBUS5: C_LDO_IN.1 R_USB_VBUS_BOTTOM_LINK.2 R_USB_VBUS_TOP_LINK.2 U_ESD.5 U_LDO.1 U_LDO.3 | length 29.8
  Top w0.5: C_LDO_IN.1 36.45,63.525 U_LDO.3 ; R_USB_VBUS_TOP_LINK.2 36.225,50.9 36.725,50.9 36.9,50.9 37.15,51.15 37.4,51.15 39.15,52.9 39.15,53.65 39.9,54.4 ; U_LDO.1 38.2,61.8 37.6,61.6 36.45,61.6 U_LDO.3 ; U_LDO.3 36.45,58.725 R_USB_VBUS_BOTTOM_LINK.2 35.65,57.925 35.65,57.9 36.15,57.9 36.4,57.65 36.65,57.65 36.9,57.4 37.15,57.4 37.4,57.15 37.65,57.15 37.9,56.9 38.15,56.9 39.15,55.9 39.15,55.15 39.9,54.4 ; 39.9,54.4 U_ESD.5 39.9,54.4
VCC_3V3: C_3V3_BULK.1 C_LDO_OUT.1 C_MCU_BULK.1 C_MCU_VDD.1 C_MCU_VUSB.1 C_SENSOR_VDD.1 C_SENSOR_VDDIO.1 J_SENSOR_IO.1 J_SWD.1 R_I2C_SCL.2 R_I2C_SDA.2 R_MCU_RESET.2 R_SENSOR_BOOT.2 R_SENSOR_RESET.2 R_SENSOR_VDD_LINK.1 R_SENSOR_VDDIO_LINK.2 U_LDO.5 U_MAIN.29 U_MAIN.40 | length 154.3
  Top w0.275: 38.309,68.903 38.594,68.628 38.59,68.241 38.587,67.854
  Top w0.3: U_MAIN.29@69.65,59.414 69.65,59.732 U_MAIN.29 U_MAIN.29@69.65,60.425 ; 70.845,56.069 71.124,55.79 71.403,55.512 ; U_MAIN.40@73.021,54.679 U_MAIN.40 73.15,54.65 73.25,54.65 73.35,54.65 73.45,54.65 73.55,54.65 73.65,54.65 73.75,54.65 U_MAIN.40@73.8,54.65
  Top w0.306: 72.3,54.676 72.631,54.678 U_MAIN.40@73.021,54.679
  Top w0.312: v1@70.566,56.347 70.845,56.069
  Top w0.325: v1@69.637,59.083 69.637,58.989 v1(69.67,58.954)
  Top w0.35: 38.025,69.178 38.309,68.903 ; 78.478,53.287 78.485,52.969 v1(78.492,52.65)
  Top w0.363: v1@70.566,56.347 v1(70.605,56.45) ; v1(93.333,41.856) 93.366,41.856 93.638,42.128
  Top w0.375: 71.403,55.512 71.683,55.233 71.935,54.967 72.188,54.7 72.241,54.676 72.3,54.676
  Top w0.387: 38.583,67.467 38.587,67.854
  Top w0.4: C_LDO_OUT.1 37.456,69.728 37.74,69.453 38.025,69.178 ; 38.583,67.467 38.58,67.08 38.576,66.693 38.572,66.306 38.569,65.919 U_LDO.5 44.613,65.7 C_3V3_BULK.1 53.678,74.765 J_SWD.1 ; v1(63.4,70.6) 63.546,70.454 63.686,70.454 63.685,70.083 63.684,69.711 63.683,69.34 63.8,69.2 63.68,68.226 63.679,67.854 63.678,67.483 63.677,67.112 63.676,66.74 63.675,66.369 63.674,65.997 63.674,65.626 63.951,65.348 64.228,65.069 64.505,64.791 64.782,64.513 65.059,64.235 65.336,63.956 65.613,63.678 C_MCU_VUSB.1 66.109,63.181 66.327,62.963 66.546,62.744 66.932,62.744 67.319,62.744 67.706,62.744 67.983,62.467 68.261,62.189 68.539,61.911 68.817,61.633 69.094,61.356 69.6,61 U_MAIN.29@69.65,60.425 ; v1@69.637,59.083 69.65,59.096 U_MAIN.29@69.65,59.414 ; U_MAIN.40@73.8,54.65 73.85,54.65 74.64,54.65 C_MCU_VDD.1 74.89,55.88 R_MCU_RESET.2 77.488,55.323 C_MCU_BULK.1 77.731,54.656 77.975,54.412 78.219,54.168 78.463,53.924 78.47,53.606 78.478,53.287 ; v1(84.618,52.615) 84.644,52.589 84.644,52.548 84.883,52.302 84.883,51.909 84.884,51.515 84.884,51.122 84.885,50.728 84.885,50.335 84.886,49.941 84.886,49.548 84.887,49.154 84.887,48.761 84.888,48.367 84.888,47.974 84.8,47.8 84.89,46.793 R_I2C_SDA.2 85.14,46.144 85.6,45.6 86.89,45.892 87.265,45.894 87.64,45.895 88.016,45.896 88.391,45.897 88.64,46.149 R_I2C_SCL.2 88.89,46.728 88.89,47.057 88.824,47.123 88.824,47.291 v1(88.8,47.306) ; v1(87.649,73.403) 87.649,66.641 C_SENSOR_VDD.1 ; 93.638,42.128 R_SENSOR_RESET.2 94.274,42.4 94.639,42.4 95.003,42.4 95.367,42.4 95.731,42.4 96.096,42.4 96.46,42.4 96.824,42.4 97.189,42.4 97.553,42.4 97.917,42.4 98.099,42.218 98.6,41.6 99.4,41.8 99.655,42.24 R_SENSOR_BOOT.2 99.91,45.95 R_SENSOR_VDDIO_LINK.2 101,47.8 100.4,48.4 100.227,48.797 99.949,49.076 99.671,49.356 99.393,49.635 99.115,49.915 98.837,50.194 98.558,50.473 98.28,50.753 98.002,51.032 97.724,51.312 97.446,51.591 97.168,51.871 R_SENSOR_VDD_LINK.1 96.84,52.2 v1(96.2,52.2) ; v1(94.977,58.049) 95.017,58.089 95.019,58.089 95.329,58.4 C_SENSOR_VDD.1 ; v1(101.582,59.818) 101.556,59.844 101.542,59.844 101.159,59.844 100.777,59.844 100.394,59.844 100.2,60.2 99.001,60.103 97.831,60.094 97.334,59.844 97.093,59.603 96.852,59.362 96.612,59.122 96.371,58.881 96.131,58.641 C_SENSOR_VDD.1 ; v1(102.81,59.269) 103.021,59.269 103.238,59.052 103.456,58.835 103.673,58.617 C_SENSOR_VDDIO.1
  Bottom w0.4: v1(63.4,70.6) 63.4,70.986 63.4,71.373 63.4,71.759 63.4,72.146 63.4,72.532 63.4,72.919 63.4,73.305 63.643,73.548 63.887,73.792 64.13,74.035 64.373,74.278 64.617,74.522 J_SWD.1 ; v1(69.67,58.954) 69.676,58.556 69.683,58.157 69.689,57.759 69.695,57.36 69.972,57.083 70.25,56.805 70.527,56.528 v1(70.605,56.45) ; v1(78.492,52.65) 78.49,52.594 78.627,52.594 78.649,52.616 79.047,52.616 79.445,52.616 79.843,52.616 80.241,52.616 80.639,52.616 81.037,52.616 81.435,52.615 81.833,52.615 82.23,52.615 82.628,52.615 83.026,52.615 83.424,52.615 83.822,52.615 84.22,52.615 v1(84.618,52.615) ; J_SENSOR_IO.1 87.51,73.547 87.614,73.443 87.614,73.438 v1(87.649,73.403) ; v1(88.8,47.306) 88.8,47.031 88.8,46.756 88.8,46.482 89.067,46.215 89.334,45.948 89.601,45.681 89.867,45.414 90.134,45.147 90.401,44.88 90.668,44.614 90.935,44.347 91.202,44.08 91.468,43.813 91.735,43.546 92.002,43.279 92.269,43.013 92.536,42.746 92.803,42.479 93.069,42.212 93.336,41.945 93.336,41.859 v1(93.333,41.856) ; v1(94.977,58.049) 94.977,53.458 96.2,52.235 v1(96.2,52.2) ; v1(101.582,59.818) 101.884,59.818 102.185,59.818 102.413,59.59 102.642,59.361 102.718,59.361 v1(102.81,59.269)
pads on no net: J_SWD.6 J_SWD.7 J_SWD.8 J_USB.5 J_USB.11 J_USB.NPTH-1 J_USB.NPTH-2 U_LDO.4 U_MAIN.1 U_MAIN.2 U_MAIN.3 U_MAIN.4 U_MAIN.5 U_MAIN.6 U_MAIN.7 U_MAIN.8 U_MAIN.9 U_MAIN.10 U_MAIN.11 U_MAIN.14 U_MAIN.15 U_MAIN.16 U_MAIN.17 U_MAIN.18 U_MAIN.19 U_MAIN.20 U_MAIN.21 U_MAIN.22 U_MAIN.23 U_MAIN.24 U_MAIN.25 U_MAIN.26 U_MAIN.27 U_MAIN.28 U_MAIN.33 U_MAIN.34 U_MAIN.35 U_MAIN.36 U_MAIN.37 U_MAIN.39 U_MAIN.43 U_MAIN.44 U_MAIN.45 U_MAIN.46 U_MAIN.49 U_MAIN.52 U_MAIN.53 U_MAIN.54 U_MAIN.55 U_MAIN.56 U_MAIN.57 U_MAIN.58 U_MAIN.59 U_MAIN.60 U_MAIN.61 U_MAIN.62 U_MAIN.63 U_MAIN.64 U_SENSOR.1 U_SENSOR.7 U_SENSOR.8 U_SENSOR.10 U_SENSOR.12 U_SENSOR.13 U_SENSOR.15 U_SENSOR.16 U_SENSOR.21 U_SENSOR.22 U_SENSOR.23 U_SENSOR.24
copper on no net:
  other v2: 37.2,54.4

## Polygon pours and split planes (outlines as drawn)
GND on Bottom (solid): 117.1,85.1 25.7,85.1 25.7,25.7 117.1,25.7
GND on Bottom (solid): 65.495,75.64 65.484,75.618 65.399,75.515 65.591,75.515 65.506,75.618
GND on Bottom (solid): 65.389,77.674 63.112,75.397 63.833,75.397 64.173,75.737 64.167,75.748 64.124,75.889 64.11,76.035 64.124,76.181 64.167,76.322 64.236,76.452 64.33,76.565 64.443,76.659 64.573,76.728 64.714,76.771 64.86,76.785 65.006,76.771 65.147,76.728 65.277,76.659 65.39,76.565 65.484,76.452 65.495,76.43 65.506,76.452 65.6,76.565 65.713,76.659 65.843,76.728 65.984,76.771 66.13,76.785 66.275,76.771 65.433,77.613 65.399,77.655
GND on Bottom (solid): 65.61,75.496 65.61,75.304 65.713,75.389 65.735,75.4 65.713,75.411
GND on Bottom (solid): 69.305,75.64 69.294,75.618 69.2,75.505 69.087,75.411 69.065,75.4 69.087,75.389 69.2,75.295 69.294,75.182 69.305,75.16 69.316,75.182 69.41,75.295 69.523,75.389 69.545,75.4 69.523,75.411 69.41,75.505 69.316,75.618
GND on Bottom (solid): 68.035,75.64 68.024,75.618 67.93,75.505 67.817,75.411 67.795,75.4 67.817,75.389 67.93,75.295 68.024,75.182 68.035,75.16 68.046,75.182 68.14,75.295 68.253,75.389 68.275,75.4 68.253,75.411 68.14,75.505 68.046,75.618
GND on Bottom (solid): 66.765,75.64 66.754,75.618 66.66,75.505 66.547,75.411 66.525,75.4 66.547,75.389 66.66,75.295 66.754,75.182 66.765,75.16 66.776,75.182 66.87,75.295 66.983,75.389 67.005,75.4 66.983,75.411 66.87,75.505 66.776,75.618
GND on Bottom (solid): 64.11,74.902 64.1,74.893 64.052,74.868 64.001,74.852 63.947,74.847 63.299,74.847 63.283,73.754 63.36,73.831 63.604,74.075 63.847,74.318 64.09,74.561 64.11,74.581
GND on Bottom (solid): 99.246,62.96 99.246,62.959 101.377,60.828 101.411,60.787 101.436,60.739 101.452,60.687 101.457,60.634 101.457,60.196 101.504,60.21 101.582,60.218 101.884,60.218 102.018,60.218
GND on Bottom (solid): 105.133,52.684 105.092,52.672 105.014,52.664 105.004,52.665 104.422,52.084 104.422,50.673 104.441,50.639 104.456,50.587 104.462,50.534 104.456,50.48 104.441,50.428 104.416,50.382 104.429,50.366 104.466,50.297 104.489,50.222 104.496,50.144 104.489,50.066 104.466,49.991 104.429,49.921 104.379,49.861 104.319,49.811 104.25,49.774 104.174,49.751 104.096,49.744 104.018,49.751 103.943,49.774 103.874,49.811 103.844,49.836 103.594,49.835 103.564,49.811 103.495,49.774 103.42,49.751 103.342,49.744 103.264,49.751 103.189,49.774 103.12,49.811 103.059,49.861 103.018,49.911 100.606,47.491 100.605,47.491 100.564,47.457 100.516,47.431 100.464,47.416 100.411,47.41 100.23,47.41 100.224,47.402 100.163,47.352 100.094,47.315 100.019,47.293 99.952,47.286 99.962,47.268 99.984,47.193 99.992,47.115 99.984,47.037 99.976,47.009 102.344,47.009 105.133,49.798
GND on Bottom (solid): 99.317,48.054 99.292,48.033 99.223,47.996 99.17,47.98 99.194,47.952 99.231,47.883 99.253,47.808 99.261,47.73 99.253,47.652 99.231,47.577 99.194,47.508 99.144,47.447 99.083,47.397 99.014,47.36 98.939,47.338 98.861,47.33 98.783,47.338 98.708,47.36 98.639,47.397 98.604,47.426 98.584,47.424 94.872,47.424 94.866,47.416 94.857,47.409 94.865,47.41 94.943,47.402 95.018,47.38 95.087,47.343 95.148,47.293 95.198,47.232 95.235,47.163 95.257,47.088 95.265,47.01 95.265,47.009 99.208,47.009 99.2,47.037 99.192,47.115 99.2,47.193 99.222,47.268 99.259,47.337 99.309,47.398 99.317,47.404

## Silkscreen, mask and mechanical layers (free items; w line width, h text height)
Top Overlay:
  text "3V3 • SWD • 2L" at 43.4,83.4 h0.48
  text "I2C 0x28 • USB-C FS" at 98.4,83.4 h0.5
  text "MSPM0G5187SPMR • NATIVE USB" at 60.4,29.9 h0.52
  text "BNO055" at 101.4,29.9 h0.55
  text "QUICK CONFIGURE • SENSOR BOARD" at 76.4,27.4 h0.65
